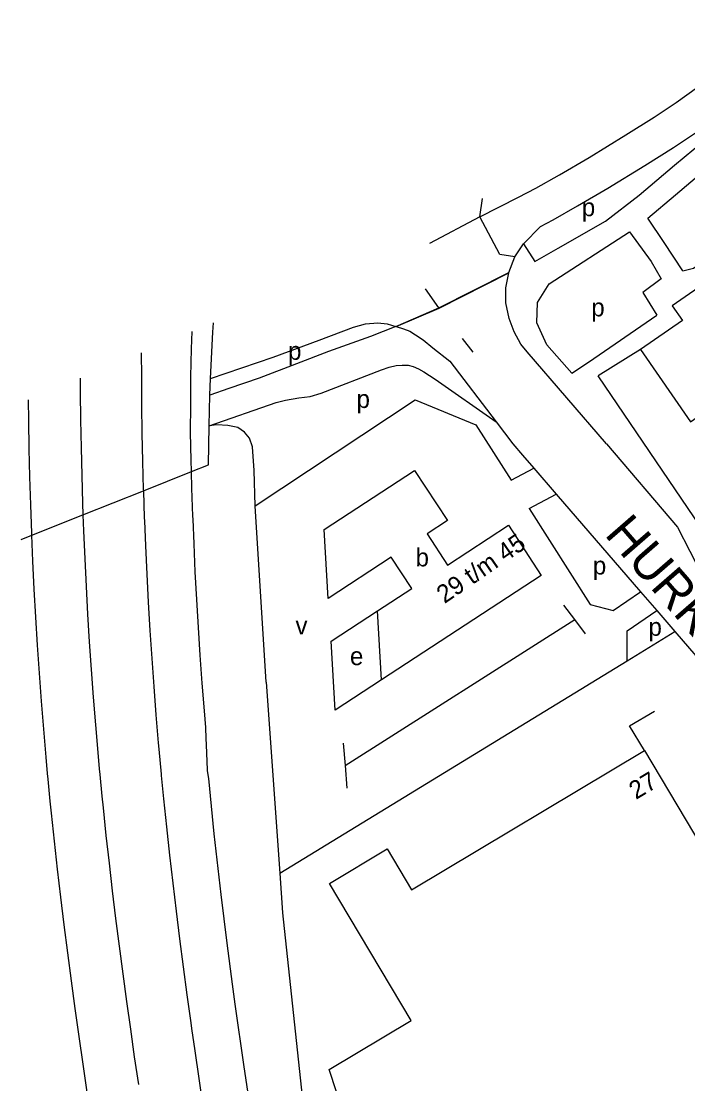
# Model space of a CAD drawing. Extents: x 157699 to 159683, y 381451 to 383293.
# Drawn here: x 157699.4 to 157847.3, y 382912.1 to 383147.8 of the extents above; entities that cross this region are included whole.
import ezdxf

# ---------------------------------------------------------------- set-up
doc = ezdxf.new("R2010")
doc.units = 0
for name, color, linetype in [('BLT_Basislijn', 7, 'Continuous'), ('BLT_Bebouwing', 7, 'Continuous'), ('BLT_Centroide', 7, 'Continuous'), ('BLT_Huisnummer_reeks', 7, 'Continuous'), ('BLT_Straatnaam_hoofdweg', 7, 'Continuous'), ('BLT_Vlakafsluiter', 7, 'Continuous')]:
    doc.layers.add(name, color=color, linetype=linetype)

msp = doc.modelspace()

# ---------------------------------------------------------------- linework, layer by layer
at = {"layer": 'BLT_Basislijn'}
for p, q in [((157808.96, 383095.5), (157810.91, 383098.37)), ((157792.11, 383084.18), (157789.09, 383088.43)), ((157741.94, 383078.83), (157742.06, 383080.91)), ((157741.39, 383068.51), (157741.94, 383078.83)), ((157799.7, 383074.39), (157797.31, 383077.42)), ((157836.87, 383074.96), (157827.41, 383069.11)), ((157794.53, 383072.4), (157804.82, 383058.89)), ((157821.58, 383069.72), (157825.32, 383072.14)), ((157741.26, 383064.85), (157741.39, 383068.51)), ((157741.13, 383058.05), (157741.26, 383064.85)), ((157751.3, 383040.28), (157786.83, 383063.81)), ((157740.99, 383049.38), (157741.13, 383058.05)), ((157804.82, 383058.89), (157808.5, 383054.05)), ((157808.5, 383054.05), (157810.68, 383051.53)), ((157810.68, 383051.53), (157813.2, 383048.62)), ((157737.2, 383047.87), (157740.99, 383049.38)), ((157808.15, 383045.96), (157813.2, 383048.62)), ((157813.2, 383048.62), (157818.15, 383042.88)), ((157713.1, 383038.29), (157726.51, 383043.62)), ((157812.13, 383039.71), (157818.15, 383042.88)), ((157818.15, 383042.88), (157836.85, 383021.23)), ((157753.77, 383001.16), (157751.3, 383040.28)), ((157699.41, 383032.85), (157701.76, 383033.78)), ((157836.85, 383021.23), (157840.46, 383017.04)), ((157822.23, 383015.08), (157819.83, 383018.28)), ((157840.46, 383017.04), (157844.49, 383012.38)), ((157771.27, 382982.66), (157822.23, 383015.08)), ((157824.63, 383011.88), (157822.23, 383015.08)), ((157833.88, 383005.9), (157844.49, 383012.38)), ((157844.49, 383012.38), (157849.12, 383007.02)), ((157756.79, 382958.83), (157833.88, 383005.9)), ((157753.77, 383001.16), (157756.79, 382958.83)), ((157770.88, 382987.64), (157771.27, 382982.66)), ((157771.27, 382982.66), (157771.67, 382977.67)), ((157756.79, 382958.83), (157757.42, 382949.97))]:
    msp.add_line(p, q, dxfattribs=at)
for points in [[(157846.26, 383092.41), (157842.08, 383098.68), (157838.45, 383104.08), (157844.6, 383109.27), (157853.89, 383117.09), (157866.2, 383127.04), (157873.42, 383132.18), (157877.44, 383135.02), (157885.1, 383140.43), (157895.62, 383147.77)], [(157801.17, 383104.39), (157809.78, 383108.73), (157813.62, 383110.73), (157818.86, 383113.74), (157825.48, 383117.58), (157833.57, 383122.6), (157839.88, 383126.51), (157844.75, 383129.74), (157849.51, 383133.12), (157855.57, 383137.29), (157862.8, 383142.22), (157866.35, 383144.66)], [(157810.91, 383098.37), (157813.42, 383094.46), (157818.57, 383097.47), (157829.09, 383103.46), (157836.52, 383109.18), (157844.39, 383115.82), (157855.14, 383124.71), (157866.91, 383133.87), (157871.51, 383137.18), (157870.88, 383138.07)], [(157810.91, 383098.37), (157814.63, 383102.24), (157817.45, 383103.7), (157822.86, 383106.81), (157829.6, 383110.72), (157837.79, 383115.8), (157844.2, 383119.77), (157849.28, 383123.14), (157854.1, 383126.57), (157860.09, 383130.69), (157867.32, 383135.61), (157870.88, 383138.07)], [(157846.26, 383092.41), (157848.61, 383092.99), (157901.92, 383129.69), (157903.93, 383130.81)], [(157801.17, 383104.39), (157789.99, 383098.45)], [(157821.58, 383069.72), (157816.08, 383075.97), (157813.82, 383080.86), (157813.99, 383085.39), (157816.56, 383089.5), (157834.41, 383101.08), (157839.22, 383094.48), (157841.41, 383090.67), (157837.33, 383087.64), (157840.45, 383082.58)], [(157807.64, 383092.03), (157808.96, 383095.5)], [(157807.71, 383081.82), (157806.99, 383085.33), (157806.97, 383088.63), (157807.62, 383091.97)], [(157807.62, 383091.97), (157807.64, 383092.03)], [(157741.39, 383068.51), (157755.3, 383073.27), (157765.51, 383077.04), (157773.11, 383079.92), (157775.84, 383080.67), (157778.52, 383080.88), (157780.63, 383080.64), (157782.57, 383080.08)], [(157829.27, 383054.04), (157811.72, 383074.41), (157810.28, 383076.12), (157808.77, 383078.86), (157807.71, 383081.82)], [(157825.32, 383072.14), (157840.45, 383082.58)], [(157737.2, 383047.87), (157737.13, 383050.38), (157737, 383056.56), (157737.01, 383062.75), (157737.08, 383068.93), (157737.22, 383075.11), (157737.35, 383078.94)], [(157782.57, 383080.08), (157776.9, 383077.86), (157767.61, 383074.5), (157760.48, 383071.75), (157752.2, 383068.61), (157745.45, 383066.32), (157741.26, 383064.85)], [(157782.57, 383080.08), (157782.64, 383080.05)], [(157782.64, 383080.05), (157784.23, 383079.54), (157785.66, 383078.99), (157786.92, 383078.23), (157788.63, 383077.13), (157790.74, 383075.32), (157794.53, 383072.4)], [(157726.06, 383074.24), (157726.07, 383068.88), (157726.12, 383062.63), (157726.2, 383056.38), (157726.33, 383050.13), (157726.5, 383043.88), (157726.51, 383043.62)], [(157741.13, 383058.05), (157755.96, 383063.23), (157758.07, 383063.75), (157761.04, 383064.21), (157763.52, 383064.51), (157765.96, 383065.31), (157779.34, 383070.43), (157781.04, 383071.05), (157782.65, 383071.38), (157783.97, 383071.49), (157785.27, 383071.45), (157786.4, 383071.19), (157787.56, 383070.68), (157788.74, 383070.02), (157791.28, 383068.39), (157804.82, 383058.89)], [(157860.92, 383026.64), (157860.67, 383026.47), (157852.89, 383037.45), (157850.23, 383035.52), (157827.41, 383069.11)], [(157712.49, 383068.58), (157712.5, 383065.5), (157712.57, 383059.34), (157712.68, 383053.18), (157712.82, 383047.02), (157713.01, 383040.86), (157713.1, 383038.29)], [(157701.76, 383033.78), (157701.74, 383034.25), (157701.51, 383040.48), (157701.33, 383046.71), (157701.18, 383052.94), (157701.07, 383059.18), (157701.02, 383063.79)], [(157786.83, 383063.81), (157800.32, 383058.23), (157808.15, 383045.96)], [(157751.3, 383040.28), (157751.08, 383048.15), (157750.71, 383053.34), (157750.06, 383055.27), (157748.99, 383056.61), (157747.44, 383057.63), (157745.25, 383058.11), (157742.79, 383058.27), (157741.13, 383058.05)], [(157829.27, 383054.04), (157845.02, 383035.53), (157850.52, 383024.91), (157858.19, 383015.35)], [(157738.03, 383025.67), (157737.75, 383031.84), (157737.53, 383037.36), (157737.5, 383038.02), (157737.3, 383044.2), (157737.2, 383047.87)], [(157726.51, 383043.62), (157726.71, 383037.63), (157726.73, 383036.95), (157726.96, 383031.38), (157727.25, 383025.13), (157727.58, 383018.89), (157727.65, 383017.62), (157727.95, 383012.65), (157728.36, 383006.41), (157728.81, 383000.17), (157729.3, 382993.94), (157729.83, 382987.71), (157729.95, 382986.28), (157730.46, 382980.77), (157730.49, 382980.49), (157731, 382975.26), (157731.65, 382969.04), (157732.33, 382962.82), (157733.04, 382956.61), (157733.79, 382950.4), (157734.56, 382944.2), (157735.36, 382938), (157736.19, 382931.8), (157737.03, 382925.61), (157737.22, 382924.31), (157737.91, 382919.42), (157738.8, 382913.23), (157740.63, 382900.86)], [(157713.1, 383038.29), (157713.23, 383034.71), (157713.49, 383028.55), (157713.79, 383022.4), (157714.13, 383016.25), (157714.5, 383010.1), (157714.92, 383003.95), (157715.37, 382997.81), (157715.86, 382991.67), (157716.39, 382985.53), (157716.72, 382981.93), (157716.84, 382980.7), (157717.3, 382975.88), (157717.57, 382973.26), (157718.21, 382967.13), (157718.89, 382961), (157719.61, 382954.87), (157720.36, 382948.73), (157721.13, 382942.6), (157721.94, 382936.46), (157722.77, 382930.33), (157723.63, 382924.19), (157724.5, 382918.05), (157725.4, 382911.91)], [(157812.13, 383039.71), (157825.7, 383018.43), (157830.74, 383017.04), (157836.85, 383021.23)], [(157714.03, 382910.23), (157713.12, 382916.4), (157712.24, 382922.58), (157711.38, 382928.76), (157710.54, 382934.94), (157709.73, 382941.13), (157708.94, 382947.32), (157708.19, 382953.51), (157707.47, 382959.7), (157706.78, 382965.9), (157706.13, 382972.09), (157705.86, 382974.74), (157705.39, 382979.62), (157705.27, 382980.87), (157704.94, 382984.5), (157704.4, 382990.71), (157703.91, 382996.93), (157703.45, 383003.14), (157703.03, 383009.36), (157702.65, 383015.58), (157702.31, 383021.8), (157702, 383028.03), (157701.76, 383033.78)], [(157753.46, 382885.31), (157748.86, 382915.85), (157746.91, 382929.75), (157746.32, 382934.14), (157745.1, 382943.29), (157743.76, 382954.1), (157742.23, 382967.56), (157741.02, 382979.8), (157740.78, 382981.48), (157740.77, 382981.75), (157740.52, 382987.23), (157740.47, 382988.64), (157740.37, 382991.12), (157740.06, 382994.82), (157739.58, 383000.98), (157739.13, 383007.15), (157738.73, 383013.32), (157738.43, 383018.24), (157738.36, 383019.49), (157738.03, 383025.67)], [(157779.35, 383001.65), (157769.07, 382994.93), (157768.2, 383010.24), (157778.45, 383016.98)], [(157833.88, 383005.9), (157833.88, 383012.53), (157840.46, 383017.04)], [(157837.7, 382985.98), (157834.41, 382991.48), (157839.91, 382994.77)], [(157757.42, 382949.97), (157774.26, 382792.55), (157775.91, 382781.48)]]:
    msp.add_lwpolyline(points, dxfattribs=at)
at = {"layer": 'BLT_Bebouwing'}
for p, q in [((157767.53, 383019.72), (157766.63, 383035.04)), ((157779.35, 383001.65), (157778.45, 383016.98))]:
    msp.add_line(p, q, dxfattribs=at)
for points in [[(157905.98, 383127.57), (157887.46, 383114.78), (157885.36, 383117.83), (157866.43, 383104.81), (157868.56, 383101.72), (157843.85, 383084.66), (157846.14, 383081.36), (157836.87, 383074.96)], [(157836.87, 383074.96), (157847.92, 383058.94), (157851.08, 383061.12), (157852.92, 383058.41), (157859.51, 383062.96), (157857.36, 383066.06), (157869.39, 383074.29)], [(157766.63, 383035.04), (157786.7, 383048.15), (157793.98, 383037), (157789.48, 383034.04), (157793.98, 383027.12), (157807.55, 383035.97)], [(157807.55, 383035.97), (157814.83, 383024.82), (157779.35, 383001.65)], [(157778.45, 383016.98), (157786.06, 383021.94), (157781.54, 383028.87), (157767.53, 383019.72)], [(157783.62, 382831.27), (157777.07, 382842.25), (157781.19, 382844.72), (157774.73, 382855.69), (157788.28, 382863.77), (157780.24, 382877.19), (157767.77, 382915.25), (157785.92, 382926.14), (157767.81, 382956.5), (157780.62, 382964.23), (157786.04, 382955.13), (157837.7, 382985.98)], [(157837.7, 382985.98), (157861.29, 382946.4), (157865.96, 382949.15), (157872.1, 382938.88), (157867.46, 382936.08), (157870.72, 382930.6), (157869.09, 382929.61), (157892.34, 382890.7)]]:
    msp.add_lwpolyline(points, dxfattribs=at)
at = {"layer": 'BLT_Vlakafsluiter'}
for p, q in [((157801.17, 383104.39), (157801.81, 383108.48)), ((157792.11, 383084.18), (157807.64, 383092.03)), ((157792.13, 383084.14), (157807.62, 383091.97)), ((157782.57, 383080.08), (157792.11, 383084.18)), ((157782.64, 383080.05), (157792.13, 383084.14)), ((157726.51, 383043.62), (157737.2, 383047.87)), ((157701.76, 383033.78), (157713.1, 383038.29))]:
    msp.add_line(p, q, dxfattribs=at)
msp.add_lwpolyline([(157808.96, 383095.5), (157805.64, 383096), (157801.17, 383104.39)], dxfattribs=at)

# ---------------------------------------------------------------- texts
at = {"layer": 'BLT_Centroide'}
for s, p in [('p', (157823.81, 383104.52)), ('p', (157825.92, 383082.31)), ('p', (157758.62, 383072.67)), ('p', (157773.82, 383061.99)), ('b', (157786.92, 383026.85)), ('p', (157826.27, 383025.04)), ('v', (157760.27, 383011.75)), ('p', (157838.61, 383011.44)), ('e', (157772.36, 383004.95))]:
    msp.add_text(s, height=4, dxfattribs=at).set_placement(p)
at = {"layer": 'BLT_Huisnummer_reeks'}
for s, rotation, p in [('29 t/m 45', 34.4589, (157793.34, 383018.48)), ('27', 30.8475, (157835.82, 382975.03))]:
    msp.add_text(s, height=4, rotation=rotation, dxfattribs=at).set_placement(p)
at = {"layer": 'BLT_Straatnaam_hoofdweg'}
msp.add_text('HURKSESTRAAT', height=8, rotation=311.0051, dxfattribs=at).set_placement((157828.67, 383033.86))

doc.saveas('drawing.dxf')
